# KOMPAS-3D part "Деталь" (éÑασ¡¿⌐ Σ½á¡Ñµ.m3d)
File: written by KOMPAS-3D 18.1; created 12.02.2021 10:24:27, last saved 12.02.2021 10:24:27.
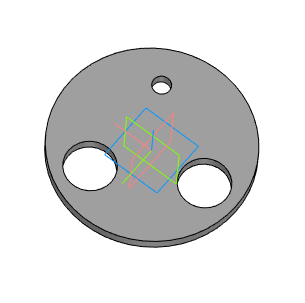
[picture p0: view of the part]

Document properties: Полное имя файла: C:\GoogleDrive\НИР\ИКИ\Компас\Верхний фланец.m3d

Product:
- Part/product: Деталь
    Масса: 1.35822

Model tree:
1. Эскиз:1
2. Элемент выдавливания:1
     Расстояние 1 = 10
3. Эскиз:2  (with: Элемент выдавливания:1)
4. Элемент выдавливания:2
     Расстояние 2 = 10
